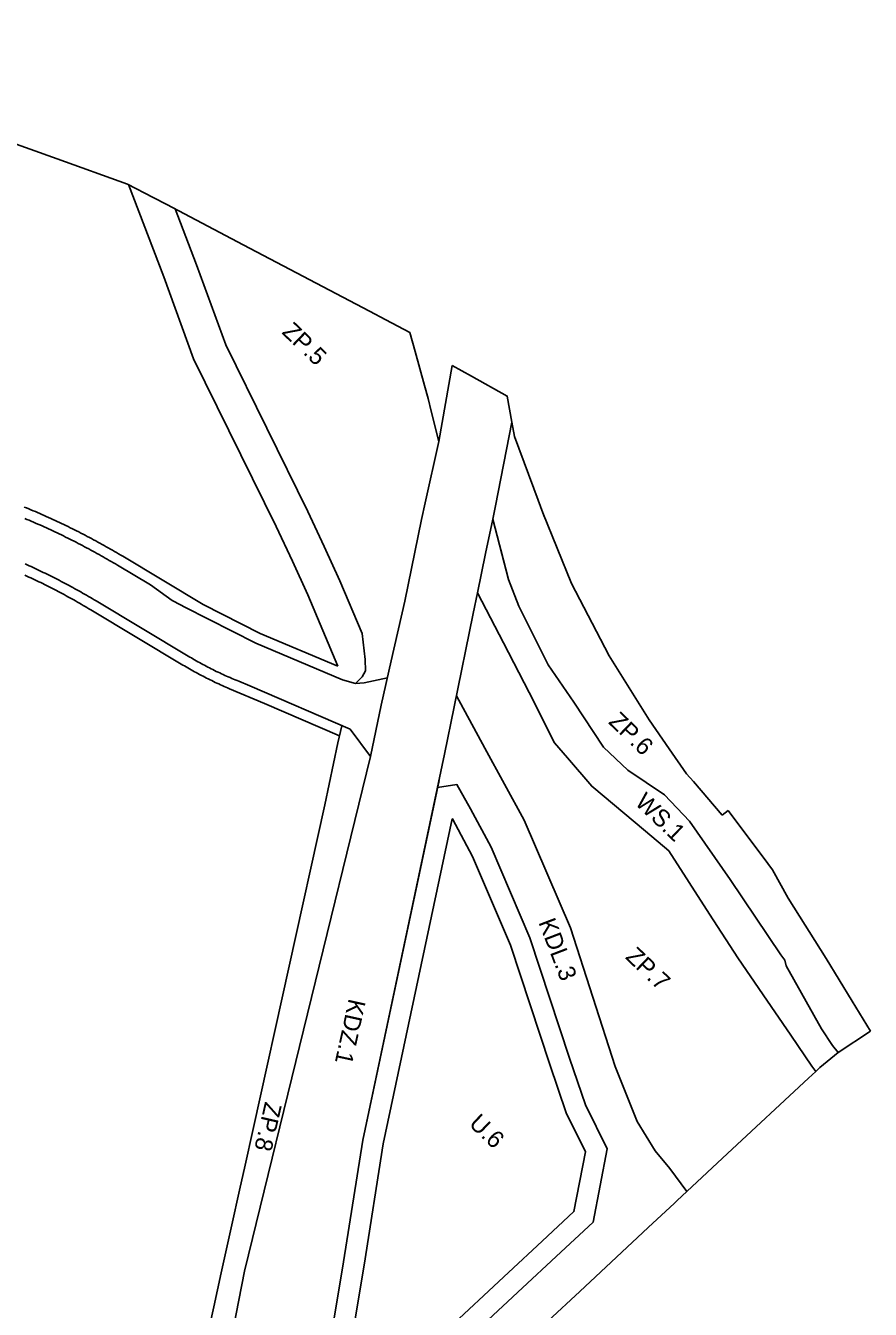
# Model space of a CAD drawing. Extents: x 7420063 to 7422255, y 5550978 to 5552824.
# Drawn here: x 7422010.7 to 7422254.7, y 5551292.7 to 5551663.3 of the extents above; entities that cross this region are included whole.
import ezdxf

# ---------------------------------------------------------------- set-up
doc = ezdxf.new("R2010")
doc.units = 0
for name, color, linetype in [('linie_rozgraniczajace', 7, 'Continuous'), ('linie_zabudowy_nieprzekraczalne', 7, 'Continuous'), ('oznaczenia_przeznaczen', 7, 'Continuous')]:
    doc.layers.add(name, color=color, linetype=linetype)

msp = doc.modelspace()

# ---------------------------------------------------------------- linework, layer by layer
at = {"layer": 'linie_rozgraniczajace'}
for p, q in [((7422130.07, 5551543.21), (7422133.89, 5551565.15)), ((7422127.83, 5551552.01), (7422130.07, 5551543.21)), ((7422168.35, 5551502.26), (7422160.06, 5551522.69)), ((7422150.12, 5551503.45), (7422145.62, 5551520.79)), ((7422046.72, 5551501.82), (7422052.99, 5551497.32)), ((7422108.46, 5551473.57), (7422115.19, 5551475.04)), ((7422104.4, 5551460.17), (7422110.29, 5551452.3)), ((7422254.65, 5551372.99), (7422245.38, 5551366.88)), ((7422236.82, 5551359.47), (7422213.4, 5551337.66)), ((7422174.57, 5551317.89), (7422178.64, 5551339.04)), ((7422213.4, 5551337.66), (7422201.69, 5551326.75)), ((7422201.69, 5551326.75), (7422198.88, 5551324.13)), ((7422198.1, 5551323.41), (7422190.47, 5551316.3)), ((7422198.88, 5551324.13), (7422198.1, 5551323.41)), ((7422163.94, 5551307.98), (7422174.57, 5551317.89)), ((7422190.47, 5551316.3), (7422181.32, 5551307.78)), ((7422154.21, 5551298.92), (7422163.94, 5551307.98)), ((7422181.32, 5551307.78), (7422170.72, 5551297.9)), ((7422170.72, 5551297.9), (7422161.62, 5551289.43))]:
    msp.add_line(p, q, dxfattribs=at)
for points in [[(7421912.21, 5551663.28), (7421915.61, 5551662.07), (7422019.81, 5551624.84), (7422040.16, 5551617.57)], [(7422040.16, 5551617.57), (7422047.57, 5551613.68), (7422051.46, 5551611.63), (7422073.51, 5551600.04)], [(7422053.88, 5551610.36), (7422060.03, 5551594.28), (7422068.5, 5551571.1), (7422068.5, 5551571.1), (7422092.15, 5551523.05), (7422096.95, 5551512.93), (7422101.46, 5551502.99), (7422107.84, 5551487.81), (7422108.8, 5551480.32), (7422108.82, 5551477.05), (7422107.84, 5551475.33), (7422105.92, 5551473.37)], [(7422073.51, 5551600.04), (7422110.05, 5551580.84)], [(7422110.05, 5551580.84), (7422114.75, 5551578.36), (7422121.63, 5551574.75)], [(7422121.63, 5551574.75), (7422123.16, 5551569.24), (7422125.86, 5551559.44)], [(7422133.89, 5551565.15), (7422139.42, 5551562.09), (7422149.8, 5551556.35), (7422151.13, 5551548.82)], [(7422125.86, 5551559.44), (7422126.91, 5551555.62), (7422127.83, 5551552.01)], [(7422146.38, 5551524.65), (7422151.13, 5551548.82)], [(7422151.13, 5551548.82), (7422151.86, 5551544.69), (7422158.7, 5551526.35), (7422160.06, 5551522.69), (7422160.57, 5551521.42)], [(7422110.29, 5551452.3), (7422113.38, 5551467.13), (7422116.3, 5551479.9), (7422120.23, 5551497.13), (7422125.02, 5551520.7), (7422126.11, 5551525.58), (7422130.07, 5551543.21)], [(7422088.9, 5551221.88), (7422094.81, 5551260.17), (7422102.52, 5551306.4), (7422108.05, 5551341.6), (7422131.71, 5551453), (7422134.47, 5551466.63), (7422139.91, 5551493.55), (7422141.2, 5551499.53), (7422143.52, 5551510.9), (7422145.62, 5551520.79), (7422146.38, 5551524.65)], [(7422010.43, 5551521.03), (7422011.06, 5551520.76), (7422011.69, 5551520.5), (7422012.32, 5551520.23), (7422012.94, 5551519.96), (7422013.57, 5551519.69), (7422014.2, 5551519.42), (7422014.82, 5551519.14), (7422015.44, 5551518.86), (7422016.07, 5551518.58), (7422016.69, 5551518.3), (7422017.31, 5551518.02), (7422017.93, 5551517.73), (7422018.55, 5551517.44), (7422019.16, 5551517.15), (7422019.78, 5551516.86), (7422020.4, 5551516.57), (7422021.01, 5551516.27), (7422021.62, 5551515.97), (7422022.24, 5551515.67), (7422022.85, 5551515.37), (7422023.46, 5551515.07), (7422024.07, 5551514.76), (7422024.68, 5551514.45), (7422025.29, 5551514.14), (7422025.89, 5551513.83), (7422026.5, 5551513.51), (7422027.1, 5551513.2), (7422027.71, 5551512.88), (7422028.31, 5551512.56), (7422028.91, 5551512.24), (7422029.51, 5551511.91), (7422030.11, 5551511.59), (7422030.7, 5551511.26), (7422031.3, 5551510.93), (7422031.9, 5551510.6), (7422032.49, 5551510.27), (7422033.08, 5551509.93), (7422033.67, 5551509.59), (7422034.27, 5551509.25), (7422034.85, 5551508.91), (7422035.44, 5551508.57), (7422036.03, 5551508.22), (7422036.61, 5551507.88), (7422037.19, 5551507.53), (7422046.72, 5551501.82)], [(7422147.92, 5551511.93), (7422150.12, 5551503.45), (7422153.12, 5551495.66), (7422161.56, 5551478.76), (7422169.04, 5551468)], [(7422010.54, 5551507.91), (7422011.13, 5551507.65), (7422011.71, 5551507.38), (7422012.3, 5551507.11), (7422012.88, 5551506.84), (7422013.46, 5551506.57), (7422014.05, 5551506.3), (7422014.63, 5551506.02), (7422015.21, 5551505.75), (7422015.79, 5551505.47), (7422016.36, 5551505.19), (7422016.94, 5551504.9), (7422017.52, 5551504.62), (7422018.09, 5551504.33), (7422018.67, 5551504.05), (7422019.24, 5551503.76), (7422019.81, 5551503.46), (7422020.38, 5551503.17), (7422020.95, 5551502.87), (7422021.52, 5551502.58), (7422022.09, 5551502.28), (7422022.66, 5551501.97), (7422023.22, 5551501.67), (7422023.79, 5551501.37), (7422024.35, 5551501.06), (7422024.91, 5551500.75), (7422025.48, 5551500.44), (7422026.04, 5551500.13), (7422026.6, 5551499.81), (7422027.15, 5551499.5), (7422027.71, 5551499.18), (7422028.27, 5551498.86), (7422028.82, 5551498.54), (7422029.38, 5551498.21), (7422029.93, 5551497.89), (7422030.48, 5551497.56), (7422031.03, 5551497.23), (7422057.62, 5551481.3), (7422058.08, 5551481.02), (7422058.55, 5551480.75), (7422059.02, 5551480.47), (7422059.49, 5551480.2), (7422059.97, 5551479.93), (7422060.44, 5551479.67), (7422060.92, 5551479.4), (7422061.39, 5551479.14), (7422061.87, 5551478.88), (7422062.35, 5551478.63), (7422062.84, 5551478.37), (7422063.32, 5551478.12), (7422063.8, 5551477.87), (7422064.29, 5551477.62), (7422064.78, 5551477.38), (7422065.27, 5551477.13), (7422065.76, 5551476.89), (7422066.25, 5551476.66), (7422066.74, 5551476.42), (7422067.23, 5551476.19), (7422067.73, 5551475.96), (7422068.23, 5551475.73), (7422068.72, 5551475.51), (7422069.22, 5551475.29), (7422069.72, 5551475.07), (7422070.23, 5551474.85), (7422070.73, 5551474.63), (7422071.23, 5551474.42), (7422071.74, 5551474.21), (7422072.24, 5551474.01), (7422075.42, 5551472.72)], [(7422168.35, 5551502.26), (7422176.69, 5551486.22), (7422179.2, 5551481.39), (7422190.76, 5551462.93), (7422196.59, 5551454.52), (7422201.6, 5551447.31), (7422203.53, 5551445.06)], [(7422052.99, 5551497.32), (7422055.39, 5551496.06), (7422056.63, 5551495.41), (7422077.13, 5551485.01), (7422102.17, 5551474.44), (7422105.92, 5551473.37), (7422108.46, 5551473.57)], [(7422238.89, 5551361.4), (7422237.8, 5551362.96), (7422231.72, 5551371.82), (7422223.72, 5551383.48), (7422216.36, 5551394.22), (7422208.2, 5551406.83), (7422196.45, 5551425.12), (7422189.69, 5551430.77), (7422174.18, 5551443.71), (7422167.19, 5551451.92), (7422163.47, 5551456.27), (7422156.08, 5551470.74), (7422148.73, 5551485.15), (7422141.2, 5551499.53)], [(7422075.42, 5551472.72), (7422104.4, 5551460.17)], [(7422180.91, 5551362.85), (7422168.09, 5551402.87), (7422154.7, 5551433.96), (7422143.27, 5551454.69), (7422135.11, 5551469.81)], [(7422169.04, 5551468), (7422177.58, 5551455), (7422184.62, 5551448.37), (7422195.19, 5551441.22), (7422202.47, 5551433.62), (7422214.21, 5551416.79), (7422228.8, 5551395.1)], [(7422073.89, 5551333.47), (7422076.5, 5551345.22), (7422097.15, 5551438.33), (7422100.89, 5551456.22), (7422102.01, 5551461.2)], [(7422051.15, 5551187.49), (7422073.86, 5551303.71), (7422110.29, 5551452.3)], [(7422108.05, 5551341.6), (7422130.09, 5551445.37)], [(7422203.53, 5551445.06), (7422211.82, 5551435.4)], [(7422167.8, 5551365.27), (7422156.33, 5551399.93), (7422145.15, 5551426.09), (7422139.19, 5551437.18), (7422135.27, 5551444.18), (7422129.66, 5551443.34)], [(7422211.82, 5551435.4), (7422213.63, 5551436.69)], [(7422213.63, 5551436.69), (7422225.01, 5551421.41), (7422226.4, 5551419.55)], [(7422226.4, 5551419.55), (7422230.89, 5551411.43)], [(7422230.89, 5551411.43), (7422241.88, 5551394.04)], [(7422245.38, 5551366.88), (7422243.77, 5551368.85), (7422240.57, 5551373.68), (7422230.32, 5551391.92), (7422229.96, 5551393.47), (7422228.8, 5551395.1)], [(7422241.88, 5551394.04), (7422249.39, 5551381.67)], [(7422249.39, 5551381.67), (7422254.65, 5551372.99)], [(7422254.65, 5551372.99), (7422254.65, 5551372.99)], [(7422245.38, 5551366.88), (7422240.1, 5551362.53), (7422238.89, 5551361.4), (7422236.82, 5551359.47)], [(7422167.8, 5551365.27), (7422172.36, 5551351.77), (7422178.64, 5551339.04)], [(7422180.91, 5551362.85), (7422187.31, 5551346.91), (7422192.54, 5551338.45), (7422196.72, 5551333.4), (7422201.69, 5551326.75)], [(7422088.9, 5551221.88), (7422094.81, 5551260.17), (7422102.52, 5551306.4), (7422108.05, 5551341.6)], [(7422070.08, 5551316.28), (7422072.68, 5551328), (7422073.89, 5551333.47)], [(7422043.39, 5551196.65), (7422045.82, 5551207.28), (7422051.17, 5551230.56), (7422065.03, 5551293.43), (7422067.2, 5551303.29), (7422067.58, 5551305.01), (7422070.08, 5551316.28)], [(7422117.55, 5551264.84), (7422131.86, 5551278.15), (7422135.66, 5551281.68), (7422154.21, 5551298.92)]]:
    msp.add_lwpolyline(points, dxfattribs=at)
at = {"layer": 'linie_zabudowy_nieprzekraczalne'}
for p, q in [((7422101.34, 5551458.23), (7422079.7, 5551467.6)), ((7422133.89, 5551434.36), (7422113.95, 5551340.51))]:
    msp.add_line(p, q, dxfattribs=at)
for points in [[(7422100.87, 5551478.35), (7422092.21, 5551498.95), (7422087.8, 5551508.68), (7422083.06, 5551518.66), (7422059.21, 5551567.13), (7422050.58, 5551590.75), (7422040.36, 5551617.47)], [(7422010.31, 5551524.32), (7422010.95, 5551524.06), (7422011.58, 5551523.8), (7422012.22, 5551523.53), (7422012.86, 5551523.26), (7422013.5, 5551522.99), (7422014.13, 5551522.71), (7422014.77, 5551522.44), (7422015.4, 5551522.16), (7422016.04, 5551521.88), (7422016.67, 5551521.6), (7422017.3, 5551521.32), (7422017.93, 5551521.03), (7422018.56, 5551520.74), (7422019.19, 5551520.45), (7422019.82, 5551520.16), (7422020.44, 5551519.87), (7422021.07, 5551519.57), (7422021.69, 5551519.27), (7422022.32, 5551518.97), (7422022.94, 5551518.67), (7422023.56, 5551518.36), (7422024.18, 5551518.06), (7422024.8, 5551517.75), (7422025.42, 5551517.44), (7422026.04, 5551517.13), (7422026.65, 5551516.81), (7422027.27, 5551516.49), (7422027.88, 5551516.18), (7422028.5, 5551515.85), (7422029.11, 5551515.53), (7422029.72, 5551515.21), (7422030.33, 5551514.88), (7422030.94, 5551514.55), (7422031.55, 5551514.22), (7422032.15, 5551513.89), (7422032.76, 5551513.55), (7422033.36, 5551513.22), (7422033.96, 5551512.88), (7422034.57, 5551512.54), (7422035.17, 5551512.2), (7422035.76, 5551511.85), (7422036.36, 5551511.5), (7422036.96, 5551511.16), (7422037.55, 5551510.81), (7422038.15, 5551510.45), (7422038.73, 5551510.1), (7422062.01, 5551496.16)], [(7422079.7, 5551467.6), (7422069.56, 5551471.87), (7422069.04, 5551472.09), (7422068.52, 5551472.32), (7422068.01, 5551472.54), (7422067.5, 5551472.77), (7422066.98, 5551473), (7422066.47, 5551473.24), (7422065.96, 5551473.47), (7422065.46, 5551473.71), (7422064.95, 5551473.95), (7422064.44, 5551474.2), (7422063.94, 5551474.44), (7422063.44, 5551474.69), (7422062.94, 5551474.94), (7422062.44, 5551475.2), (7422061.94, 5551475.46), (7422061.44, 5551475.71), (7422060.95, 5551475.98), (7422060.45, 5551476.24), (7422059.96, 5551476.51), (7422059.47, 5551476.78), (7422058.98, 5551477.05), (7422058.49, 5551477.32), (7422058, 5551477.6), (7422057.52, 5551477.88), (7422057.04, 5551478.16), (7422056.56, 5551478.44), (7422056.09, 5551478.72), (7422029.49, 5551494.66), (7422028.95, 5551494.98), (7422028.4, 5551495.31), (7422027.86, 5551495.63), (7422027.31, 5551495.94), (7422026.77, 5551496.26), (7422026.22, 5551496.58), (7422025.67, 5551496.89), (7422025.12, 5551497.2), (7422024.57, 5551497.51), (7422024.02, 5551497.82), (7422023.47, 5551498.12), (7422022.91, 5551498.43), (7422022.36, 5551498.73), (7422021.8, 5551499.03), (7422021.24, 5551499.33), (7422020.69, 5551499.62), (7422020.13, 5551499.92), (7422019.57, 5551500.21), (7422019, 5551500.5), (7422018.44, 5551500.79), (7422017.88, 5551501.08), (7422017.32, 5551501.37), (7422016.75, 5551501.65), (7422016.18, 5551501.93), (7422015.62, 5551502.21), (7422015.05, 5551502.49), (7422014.48, 5551502.77), (7422013.91, 5551503.04), (7422013.34, 5551503.31), (7422012.77, 5551503.59), (7422012.19, 5551503.85), (7422011.62, 5551504.12), (7422011.05, 5551504.39), (7422010.47, 5551504.65)], [(7422062.01, 5551496.16), (7422078.44, 5551487.82), (7422100.87, 5551478.35)], [(7422162.1, 5551363.37), (7422150.72, 5551397.81), (7422139.74, 5551423.48), (7422133.93, 5551434.3), (7422133.89, 5551434.36)], [(7422172.37, 5551338.2), (7422166.8, 5551349.47), (7422162.1, 5551363.37)], [(7422113.95, 5551340.51), (7422108.45, 5551305.44), (7422100.38, 5551257.09)], [(7422100.38, 5551257.09), (7422104.27, 5551260.7), (7422113.46, 5551269.24), (7422127.77, 5551282.54), (7422131.57, 5551286.07), (7422150.12, 5551303.32), (7422159.85, 5551312.37), (7422169.05, 5551320.95), (7422172.37, 5551338.2)]]:
    msp.add_lwpolyline(points, dxfattribs=at)

# ---------------------------------------------------------------- texts
at = {"layer": 'oznaczenia_przeznaczen'}
for s, rotation, p in [('ZP.5', 316.2133, (7422084.46, 5551574.57)), ('ZP.6', 316.2133, (7422178.78, 5551462.04)), ('WS.1', 316.2133, (7422186.41, 5551438.7)), ('KDL.3', 290.9097, (7422158.74, 5551404.46)), ('ZP.7', 316.2133, (7422183.66, 5551394.17)), ('KDZ.1', 257.5978, (7422104.06, 5551382.61)), ('ZP.8', 257.1677, (7422079.86, 5551352.82)), ('U.6', 316.2133, (7422138.45, 5551345.98))]:
    msp.add_text(s, height=5, rotation=rotation, dxfattribs=at).set_placement(p)

doc.saveas('drawing.dxf')
